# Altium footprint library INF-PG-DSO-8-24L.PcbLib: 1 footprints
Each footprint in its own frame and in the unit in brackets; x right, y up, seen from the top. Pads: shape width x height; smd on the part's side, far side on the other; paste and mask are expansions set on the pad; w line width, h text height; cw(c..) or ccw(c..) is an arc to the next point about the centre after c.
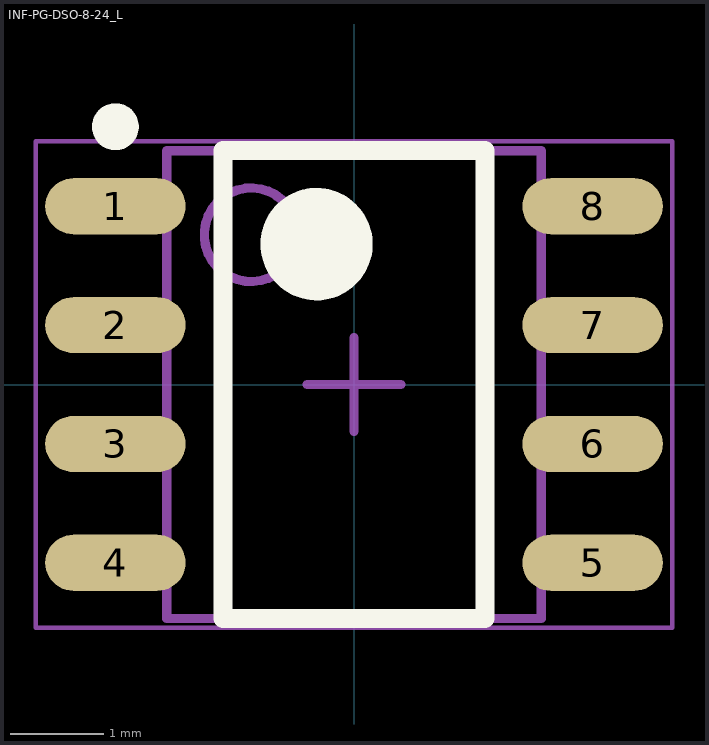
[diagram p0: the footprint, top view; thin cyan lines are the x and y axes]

## INF-PG-DSO-8-24_L [mm] "SOP, 8-Leads, Body 4.9x3.9mm, Pitch 1.27mm, IPC High Density"
height 1.75
pads (8):
  oval 1.5x0.6 smd: 1(-2.55,1.905) 2(-2.55,0.635) 3(-2.55,-0.635) 4(-2.55,-1.905) 5(2.55,-1.905) 6(2.55,-0.635) 7(2.55,0.635) 8(2.55,1.905)
Top Overlay:
  circle w0.6: c-0.4,1.5 r0.3
  circle w0.25: c-2.55,2.755 r0.125
  lines w0.2: -1.4,-2.5 1.4,-2.5 1.4,2.5 -1.4,2.5 -1.4,-2.5
Mechanical 13:
  circle w0.1: c-1.1,1.6 r0.5
  lines w0.1: -2,-2.5 2,-2.5 2,2.5 -2,2.5 -2,-2.5
Mechanical 15:
  lines w0.05: -3.4,-2.6 3.4,-2.6 3.4,2.6 -3.4,2.6 -3.4,-2.6
  lines w0.1: -0.5,0 0.5,0 ; 0,-0.5 0,0.5
3D body: height 1.75, standoff 0.1, extent -2,-2.5 2,2.5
